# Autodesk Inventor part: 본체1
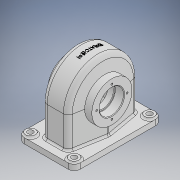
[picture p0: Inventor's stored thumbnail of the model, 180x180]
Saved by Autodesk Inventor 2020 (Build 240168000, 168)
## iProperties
Created: 2025-05
Part Number: 본체1
Material: 일반
Document SubType Name: Modeling
Designer: CA01
Density: 1 g/cm^3
Appearance: 기본값
Author: CA01
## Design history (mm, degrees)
sketch "스케치2"
  geometry: L1 (30.051, 0)-(-30.051, 0); L2 (-30.051, 0)-(-20, 57); L3 (-20, 57)-(20, 57); L4 (20, 57)-(30.051, 0); L5 (0, -3231.553)-(0, 3231.553) reference; L6 (-30.051, 0)-(-20, -57); L7 (-20, -57)-(20, -57); L8 (20, -57)-(30.051, 0); L9 (0, 3231.553)-(0, -3231.553); L10 (12, 0)-(-12, 0); L11 (-12, 0)-(-12, 24); L12 (-12, 24)-(12, 24); L13 (12, 24)-(12, 0); L14 (12, -24)-(12, 0); L15 (-12, -24)-(12, -24); L16 (-12, 0)-(-12, -24); L17 (-25.127, -0.868)-(-15.805, 52); L18 (-15.805, 52)-(15.805, 52); L19 (15.805, 52)-(25.127, -0.868); L20 (-25.127, 0.868)-(-15.805, -52); L21 (-15.805, -52)-(15.805, -52); L22 (15.805, -52)-(25.127, 0.868); L23 (20.742, 24)-(-20.742, 24); 8 further points
  constraints: 44 end point, 6 symmetric about line, 3 horizontal, 3 midpoint, 3 parallel, 3 point on line, 2 coincident, 1 perpendicular, 6 other
  dimensions: "d4" = 57 distance between parallel lines of L1 L3; "d6" = 20 deg angle of L4 L2; "d7" = 40 distance of L2.end L3.end; "d67" = 24 distance of L11.end L12.end; "d68" = 24 distance of L12.end L10.start; "d69" = 5 distance between parallel lines of L2 L17; "d70" = 5 distance between parallel lines of L6 L20
revolve "회전1" stored, may be unused: angle "d8" = 90 deg
extrude "돌출1" join sketch "스케치2" distance "d9" = 60; taper "d10" = 0 deg
sketch "스케치3"
  geometry: L1 (46, 72)-(-46, 72); L2 (-46, 72)-(-46, -72); L3 (-46, -72)-(46, -72); L4 (46, -72)-(46, 72); 3 further points
  constraints: 8 end point, 2 midpoint, 2 parallel, 1 horizontal, 1 horizontal alignment, 1 perpendicular, 1 vertical alignment
  dimensions: "d11" = 92 distance of L1.start L1.end; "d12" = 144 distance of L3.end L1.start
extrude "돌출2" join sketch "스케치3" distance "d13" = 9; taper "d14" = 0 deg
fillet "모깎기1" dims "d15" = 10
fillet "모깎기2" dims "d16" = 8
node "작업 평면1"
node "작업 평면2"
sketch "스케치4"
  geometry: C1 r 33 at (0, 0); A1 r 57 centre (0, 0) between (0, -57) and (0, 57) reference; 1 further point
  constraints: 2 coincident, 1 centre point
  dimensions: "d24" = 66 diameter of C1
extrude "돌출3" join sketch "스케치4" stored distance "d25" = 9; taper "d26" = 0 deg
sketch "스케치5"
  geometry: C1 r 33 at (0, 0); A1 r 57 centre (0, 0) between (0, -57) and (0, 57) reference; 1 further point
  constraints: 1 centre point, 1 coincident
  dimensions: "d27" = 66 diameter of C1
extrude "돌출4" join sketch "스케치5" stored distance "d28" = 9; taper "d29" = 0 deg
sketch "스케치6"
  geometry: L1 (36, 33)-(36, -33) reference; L2 (36, -20)-(21.6, -20); L3 (21, -19.4)-(21, -17.5); L4 (21, -17.5)-(-21, -17.5); L5 (-21, -17.5)-(-21, -19.4); L6 (-21.6, -20)-(-36, -20); L7 (-36, -20)-(-36, 0); L8 (-36, 33)-(-36, -33) reference; L9 (36, -20)-(36, 0); L10 (-36, 0)-(36, 0); A1 r 0.6 centre (21.6, -19.4) between (21, -19.4) and (21.6, -20); A2 r 0.6 centre (-21.6, -19.4) between (-21.6, -20) and (-21, -19.4); 3 further points
  constraints: 16 end point, 5 point on line, 4 perpendicular, 4 point on circle, 4 tangent, 2 centre point, 2 midpoint, 2 vertical, 1 equal radius, 1 horizontal
  dimensions: "d31" = 40 diameter of L2 L10; "d32" = 35 diameter of L4 L10; "d33" = 40 diameter of L6 L10; "d34" = 15 distance of point (-21, -20) L6.end; "d35" = 15 distance of L2.start point (21, -20); "d37" = 0.6 radius of A1
revolve "회전2" sketch "스케치6" stored, may be unused: angle "d38" = 90 deg
chamfer "모따기1" distance "d39" = 1; stored, may be unused: second distance "d40" = 2, angle "d41" = 45 deg
sketch "스케치8"
  geometry: 2 further points
  constraints: 2 coincident, 1 other
feature "엠보싱1" sketch "스케치8" dims "d4" = 57, "d6" = 20 deg, "d7" = 40, "d15" = 10, "d43" = 0.5, "d44" = 0, "d67" = 24, "d68" = 24, "d69" = 5, "d70" = 5
sketch "스케치9" dims "d52" = 50
  geometry: L1 (0, 0)-(0, 25); 2 further points
  constraints: 2 coincident, 2 end point, 1 vertical, 1 vertical alignment, 2 other
hole "구멍1" sketch "스케치9" at (0, 25) diameter "d45" = 3.242; stored, may be unused: countersink angle "d49" = 90 deg, drill point angle "d51" = 118 deg; dims "d46" = 8, "d47" = 4, "d48" = 2, "d50" = 10
sketch "스케치10"
  geometry: L1 (0, 0)-(0, 25); C1 r 25 at (0, 0); C2 r 1.621 at (0, 25) reference; 2 further points
  constraints: 2 coincident, 2 end point, 1 centre point, 1 vertical
  dimensions: "d63" = 50 diameter of C1
hole "구멍2" sketch "스케치10" at (0, 25) diameter "d56" = 3.242; stored, may be unused: countersink angle "d60" = 90 deg, drill point angle "d62" = 118 deg; dims "d57" = 8, "d58" = 4, "d59" = 2, "d61" = 10
sketch "스케치11"
  geometry: 1 further point
sketch "스케치12"
  geometry: 1 further point
sketch "스케치13" dims "d4" = 57, "d6" = 20 deg, "d7" = 40, "d67" = 24, "d68" = 24, "d69" = 5, "d70" = 5
  geometry: L1 (-21.166, -50.389)-(-29.806, -1.389) reference; L2 (13.287, -57)-(-13.287, -57) reference; L3 (29.806, -1.389)-(21.166, -50.389) reference; L4 (21.166, 50.389)-(29.806, 1.389) reference; L5 (-13.287, 57)-(13.287, 57) reference; L6 (-29.806, 1.389)-(-21.166, 50.389) reference; L7 (-24.882, -0.521)-(-16.242, -49.521); L8 (-13.287, -52)-(13.287, -52); L9 (16.242, -49.521)-(24.882, -0.521); L10 (24.882, 0.521)-(16.242, 49.521); L11 (13.287, 52)-(-13.287, 52); L12 (-16.242, 49.521)-(-24.882, 0.521); A1 r 8 centre (-13.287, -49) between (-21.166, -50.389) and (-13.287, -57) reference; A2 r 8 centre (13.287, -49) between (13.287, -57) and (21.166, -50.389) reference; A3 r 8 centre (21.927, 0) between (29.806, -1.389) and (29.806, 1.389) reference; A4 r 8 centre (13.287, 49) between (21.166, 50.389) and (13.287, 57) reference; A5 r 8 centre (-13.287, 49) between (-13.287, 57) and (-21.166, 50.389) reference; A6 r 8 centre (-21.927, 0) between (-29.806, 1.389) and (-29.806, -1.389) reference; A7 r 3 centre (-13.287, -49) between (-16.242, -49.521) and (-13.287, -52); A8 r 3 centre (13.287, -49) between (13.287, -52) and (16.242, -49.521); A9 r 3 centre (21.927, 0) between (24.882, -0.521) and (24.882, 0.521); A10 r 3 centre (13.287, 49) between (16.242, 49.521) and (13.287, 52); A11 r 3 centre (-13.287, 49) between (-13.287, 52) and (-16.242, 49.521); A12 r 3 centre (-21.927, 0) between (-24.882, 0.521) and (-24.882, -0.521); 1 further point
  constraints: 12 end point, 12 point on circle, 6 centre point, 11 other
  dimensions: "d71" = 5 distance between parallel lines of L1 L7
extrude "돌출5" cut sketch "스케치13" distance "d72" = 36; taper "d73" = 0 deg
sketch "스케치14"
  geometry: L1 (-46, 62)-(-46, -62) reference; L2 (-36, -72)-(36, -72) reference; L3 (46, -62)-(46, 62) reference; L4 (36, 72)-(-36, 72) reference; L5 (-21.166, 50.389)-(-29.806, 1.389) reference; L6 (13.287, 57)-(-13.287, 57) reference; L7 (29.806, 1.389)-(21.166, 50.389) reference; L8 (21.166, -50.389)-(29.806, -1.389) reference; L9 (-13.287, -57)-(13.287, -57) reference; L10 (-29.806, -1.389)-(-21.166, -50.389) reference; C1 r 8 at (36, 62); C2 r 8 at (36, -62); C3 r 8 at (-36, -62); C4 r 8 at (-36, 62); A1 r 10 centre (-36, 62) between (-36, 72) and (-46, 62) reference; A2 r 10 centre (-36, -62) between (-46, -62) and (-36, -72) reference; A3 r 10 centre (36, -62) between (36, -72) and (46, -62) reference; A4 r 10 centre (36, 62) between (46, 62) and (36, 72) reference; A5 r 8 centre (-13.287, 49) between (-13.287, 57) and (-21.166, 50.389) reference; A6 r 8 centre (13.287, 49) between (21.166, 50.389) and (13.287, 57) reference; A7 r 8 centre (21.927, 0) between (29.806, -1.389) and (29.806, 1.389) reference; A8 r 8 centre (13.287, -49) between (13.287, -57) and (21.166, -50.389) reference; A9 r 8 centre (-13.287, -49) between (-21.166, -50.389) and (-13.287, -57) reference; A10 r 8 centre (-21.927, 0) between (-29.806, 1.389) and (-29.806, -1.389) reference; 1 further point
  constraints: 4 centre point, 4 coincident
  dimensions: "d74" = 16 diameter of C1; "d75" = 16 diameter of C2; "d76" = 16 diameter of C3; "d77" = 16 diameter of C4
extrude "돌출6" join sketch "스케치14" distance "d78" = 3; taper "d79" = 0 deg
sketch "스케치15"
  geometry: C1 r 8 at (0, 0) reference; C2 r 4.5 at (0, 0); C3 r 8 at (72, 0) reference; C4 r 8 at (72, -124) reference; C5 r 8 at (0, -124) reference; C6 r 4.5 at (72, 0); C7 r 4.5 at (72, -124); C8 r 4.5 at (0, -124); 1 further point
  constraints: 4 centre point, 4 coincident
  dimensions: "d81" = 9 diameter of C2; "d84" = 9 diameter of C6; "d85" = 9 diameter of C7; "d86" = 9 diameter of C8
extrude "돌출7" cut sketch "스케치15" distance "d82" = 12; taper "d83" = 0 deg
fillet "모깎기5" dims "d87" = 3
sketch "스케치16"
  geometry: L1 (12, 24)-(-12, 24); L2 (-12, 24)-(-12, -24); L3 (-12, -24)-(12, -24); L4 (12, -24)-(12, 24); L5 (13.287, 0)-(13.287, -51) reference; L6 (13.287, 0)-(-13.287, 0) reference; L7 (13.287, 0)-(-13.287, 0); 4 further points
  constraints: 10 end point, 2 parallel, 2 perpendicular, 1 horizontal, 1 midpoint, 1 vertical alignment
  dimensions: "d88" = 24 distance of L1.start L1.end; "d89" = 24 distance from line of point (0, 0) L1; "d90" = 24 distance from line of L3 point (0, 0)
revolve "회전3" sketch "스케치16" stored, may be unused: angle "d91" = 90 deg
fillet "모깎기6" dims "d92" = 3
sketch "스케치17"
  geometry: 1 further point
node "솔리드1"
pattern_circular "원형 패턴1" dims angle "d54" = 360 deg
pattern_circular "원형 패턴2" dims angle "d65" = 360 deg
node "투영된 루프1"
node "투영된 루프2"
node "투영된 루프3"
node "투영된 루프4"
node "투영된 루프5"
feature "A9D066F2-1C7D-4E18-AEED-F7BC21143FA4" dims "d45" = 3.242, "d46" = 8, "d47" = 4, "d48" = 2, "d49" = 90 deg, "d50" = 10, "d51" = 118 deg
other parameters: "d22" = 36, "d23" = -36
